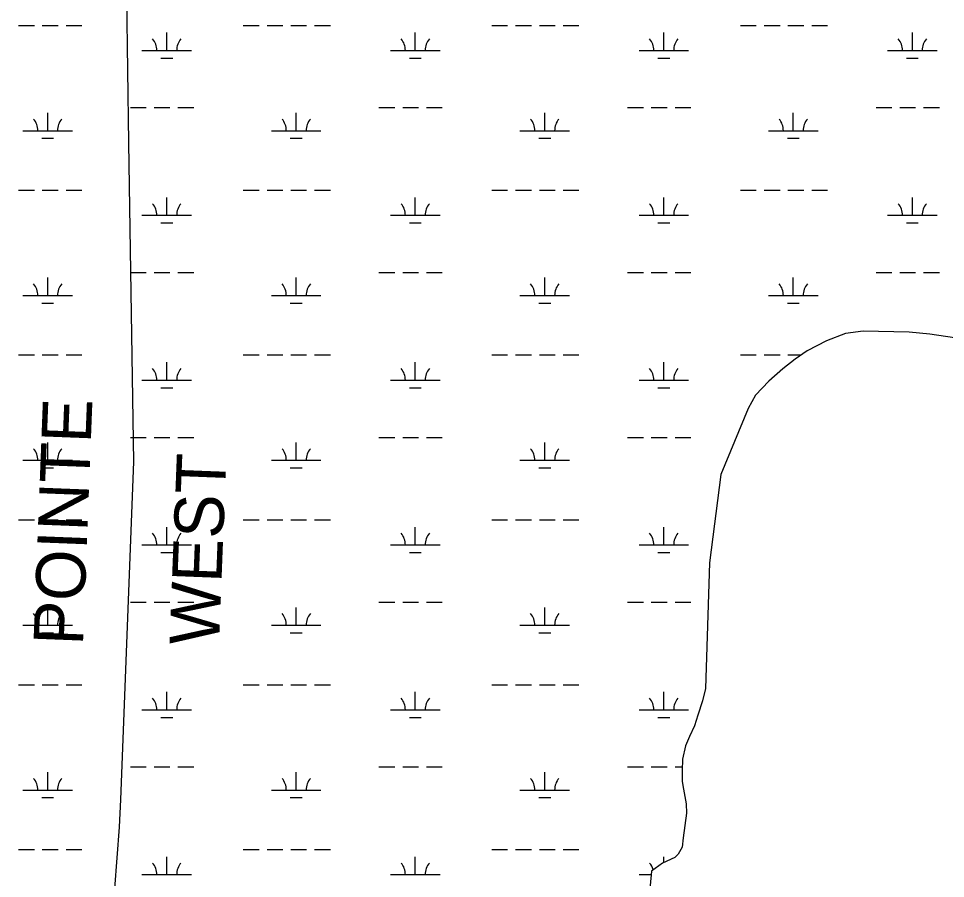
# Model space of a CAD drawing. Extents: x 3161564 to 3199464, y 849354 to 874788.
# Drawn here: x 3177599 to 3179471, y 861984 to 863719 of the extents above; entities that cross this region are included whole.
import ezdxf

# ---------------------------------------------------------------- set-up
doc = ezdxf.new("R2010")
doc.units = 0
for name, color, linetype in [('V-TOPO-BNDY', 7, 'Continuous'), ('V-TOPO-GNAM-IDEN', 7, 'Continuous'), ('V-WETL-SWMP', 7, 'Continuous')]:
    doc.layers.add(name, color=color, linetype=linetype)

msp = doc.modelspace()

# ---------------------------------------------------------------- linework, layer by layer
at = {"layer": 'V-TOPO-BNDY'}
for p, q in [((3177821.5, 863468.4), (3177816.7, 863804.9)), ((3177823.9, 863294.4), (3177821.5, 863468.4)), ((3177831.7, 862824.6), (3177823.9, 863294.4)), ((3177804.9, 862143), (3177831.7, 862824.6)), ((3177802.7, 862086.9), (3177804.9, 862143)), ((3177793, 861963), (3177802.7, 862086.9))]:
    msp.add_line(p, q, dxfattribs=at)
at = {"layer": 'V-WETL-SWMP'}
for p, q in [((3177598.6, 863705.4), (3177630.6, 863705.4)), ((3177646.6, 863705.4), (3177678.6, 863705.4)), ((3177694.6, 863705.4), (3177726.6, 863705.4)), ((3178052.5, 863705.4), (3178084.5, 863705.4)), ((3178100.5, 863705.4), (3178132.5, 863705.4)), ((3178148.5, 863705.4), (3178180.5, 863705.4)), ((3178196.5, 863705.4), (3178228.5, 863705.4)), ((3178554.4, 863705.4), (3178586.4, 863705.4)), ((3178602.4, 863705.4), (3178634.4, 863705.4)), ((3178650.4, 863705.4), (3178682.4, 863705.4)), ((3178698.4, 863705.4), (3178730.4, 863705.4)), ((3179056.4, 863705.4), (3179088.4, 863705.4)), ((3179104.4, 863705.4), (3179136.4, 863705.4)), ((3179152.4, 863705.4), (3179184.4, 863705.4)), ((3179200.4, 863705.4), (3179232.4, 863705.4)), ((3177897.9, 863654.7), (3177897.9, 863690.7)), ((3178399.9, 863654.7), (3178399.9, 863690.7)), ((3178901.8, 863654.7), (3178901.8, 863690.7)), ((3179403.7, 863654.7), (3179403.7, 863690.7)), ((3177847.9, 863654.7), (3177947.9, 863654.7)), ((3177885.9, 863639.3), (3177909.9, 863639.3)), ((3178349.9, 863654.7), (3178449.9, 863654.7)), ((3178387.9, 863639.3), (3178411.9, 863639.3)), ((3178851.8, 863654.7), (3178951.8, 863654.7)), ((3178889.8, 863639.3), (3178913.8, 863639.3)), ((3179353.7, 863654.7), (3179453.7, 863654.7)), ((3179391.7, 863639.3), (3179415.7, 863639.3)), ((3177657.5, 863492.8), (3177657.5, 863528.8)), ((3177824.5, 863539.3), (3177856.5, 863539.3)), ((3177872.5, 863539.3), (3177904.5, 863539.3)), ((3177920.5, 863539.3), (3177952.5, 863539.3)), ((3178159.4, 863492.8), (3178159.4, 863528.8)), ((3178326.4, 863539.3), (3178358.4, 863539.3)), ((3178374.4, 863539.3), (3178406.4, 863539.3)), ((3178422.4, 863539.3), (3178454.4, 863539.3)), ((3178661.3, 863492.8), (3178661.3, 863528.8)), ((3178828.4, 863539.3), (3178860.4, 863539.3)), ((3178876.4, 863539.3), (3178908.4, 863539.3)), ((3178924.4, 863539.3), (3178956.4, 863539.3)), ((3179163.2, 863492.8), (3179163.2, 863528.8)), ((3179330.3, 863539.3), (3179362.3, 863539.3)), ((3179378.3, 863539.3), (3179410.3, 863539.3)), ((3179426.3, 863539.3), (3179458.3, 863539.3)), ((3177607.5, 863492.8), (3177707.5, 863492.8)), ((3178109.4, 863492.8), (3178209.4, 863492.8)), ((3178611.3, 863492.8), (3178711.3, 863492.8)), ((3179113.2, 863492.8), (3179213.2, 863492.8)), ((3177645.5, 863477.4), (3177669.5, 863477.4)), ((3178147.4, 863477.4), (3178171.4, 863477.4)), ((3178649.3, 863477.4), (3178673.3, 863477.4)), ((3179151.2, 863477.4), (3179175.2, 863477.4)), ((3177598.6, 863372.8), (3177630.6, 863372.8)), ((3177646.6, 863372.8), (3177678.6, 863372.8)), ((3177694.6, 863372.8), (3177726.6, 863372.8)), ((3177897.9, 863322), (3177897.9, 863358)), ((3178052.5, 863372.8), (3178084.5, 863372.8)), ((3178100.5, 863372.8), (3178132.5, 863372.8)), ((3178148.5, 863372.8), (3178180.5, 863372.8)), ((3178196.5, 863372.8), (3178228.5, 863372.8)), ((3178399.9, 863322), (3178399.9, 863358)), ((3178554.4, 863372.8), (3178586.4, 863372.8)), ((3178602.4, 863372.8), (3178634.4, 863372.8)), ((3178650.4, 863372.8), (3178682.4, 863372.8)), ((3178698.4, 863372.8), (3178730.4, 863372.8)), ((3178901.8, 863322), (3178901.8, 863358)), ((3179056.4, 863372.8), (3179088.4, 863372.8)), ((3179104.4, 863372.8), (3179136.4, 863372.8)), ((3179152.4, 863372.8), (3179184.4, 863372.8)), ((3179200.4, 863372.8), (3179232.4, 863372.8)), ((3179403.7, 863322), (3179403.7, 863358)), ((3177847.9, 863322), (3177947.9, 863322)), ((3178349.9, 863322), (3178449.9, 863322)), ((3178851.8, 863322), (3178951.8, 863322)), ((3179353.7, 863322), (3179453.7, 863322)), ((3177885.9, 863306.6), (3177909.9, 863306.6)), ((3178387.9, 863306.6), (3178411.9, 863306.6)), ((3178889.8, 863306.6), (3178913.8, 863306.6)), ((3179391.7, 863306.6), (3179415.7, 863306.6)), ((3177657.5, 863160.2), (3177657.5, 863196.2)), ((3177824.5, 863206.6), (3177856.5, 863206.6)), ((3177872.5, 863206.6), (3177904.5, 863206.6)), ((3177920.5, 863206.6), (3177952.5, 863206.6)), ((3178159.4, 863160.2), (3178159.4, 863196.2)), ((3178326.4, 863206.6), (3178358.4, 863206.6)), ((3178374.4, 863206.6), (3178406.4, 863206.6)), ((3178422.4, 863206.6), (3178454.4, 863206.6)), ((3178661.3, 863160.2), (3178661.3, 863196.2)), ((3178828.4, 863206.6), (3178860.4, 863206.6)), ((3178876.4, 863206.6), (3178908.4, 863206.6)), ((3178924.4, 863206.6), (3178956.4, 863206.6)), ((3179163.2, 863160.2), (3179163.2, 863196.2)), ((3179330.3, 863206.6), (3179362.3, 863206.6)), ((3179378.3, 863206.6), (3179410.3, 863206.6)), ((3179426.3, 863206.6), (3179458.3, 863206.6)), ((3177607.5, 863160.2), (3177707.5, 863160.2)), ((3178109.4, 863160.2), (3178209.4, 863160.2)), ((3178611.3, 863160.2), (3178711.3, 863160.2)), ((3179113.2, 863160.2), (3179213.2, 863160.2)), ((3177645.5, 863144.7), (3177669.5, 863144.7)), ((3178147.4, 863144.7), (3178171.4, 863144.7)), ((3178649.3, 863144.7), (3178673.3, 863144.7)), ((3179151.2, 863144.7), (3179175.2, 863144.7)), ((3179268.5, 863083.4), (3179230, 863069)), ((3179304.2, 863087.9), (3179268.5, 863083.4)), ((3179397.1, 863086.2), (3179304.2, 863087.9)), ((3179439.2, 863081.9), (3179397.1, 863086.2)), ((3179488.5, 863074.5), (3179439.2, 863081.9)), ((3179230, 863069), (3179191, 863048.2)), ((3177598.6, 863040.1), (3177630.6, 863040.1)), ((3177646.6, 863040.1), (3177678.6, 863040.1)), ((3177694.6, 863040.1), (3177726.6, 863040.1)), ((3178052.5, 863040.1), (3178084.5, 863040.1)), ((3178100.5, 863040.1), (3178132.5, 863040.1)), ((3178148.5, 863040.1), (3178180.5, 863040.1)), ((3178196.5, 863040.1), (3178228.5, 863040.1)), ((3178554.4, 863040.1), (3178586.4, 863040.1)), ((3178602.4, 863040.1), (3178634.4, 863040.1)), ((3178650.4, 863040.1), (3178682.4, 863040.1)), ((3178698.4, 863040.1), (3178730.4, 863040.1)), ((3179056.4, 863040.1), (3179088.4, 863040.1)), ((3179104.4, 863040.1), (3179136.4, 863040.1)), ((3179152.4, 863040.1), (3179178.9, 863040.1)), ((3179191, 863048.2), (3179166.7, 863031.9)), ((3177897.9, 862989.4), (3177897.9, 863025.4)), ((3178399.9, 862989.4), (3178399.9, 863025.4)), ((3178901.8, 862989.4), (3178901.8, 863025.4)), ((3179166.7, 863031.9), (3179142, 863012.1)), ((3179142, 863012.1), (3179114.1, 862987.5)), ((3177847.9, 862989.4), (3177947.9, 862989.4)), ((3178349.9, 862989.4), (3178449.9, 862989.4)), ((3178851.8, 862989.4), (3178951.8, 862989.4)), ((3179114.1, 862987.5), (3179087.1, 862958.9)), ((3177885.9, 862973.9), (3177909.9, 862973.9)), ((3178387.9, 862973.9), (3178411.9, 862973.9)), ((3178889.8, 862973.9), (3178913.8, 862973.9)), ((3179087.1, 862958.9), (3179072.4, 862932.4)), ((3179072.4, 862932.4), (3179016.9, 862798.6)), ((3177824.5, 862873.9), (3177856.5, 862873.9)), ((3177872.5, 862873.9), (3177904.5, 862873.9)), ((3177920.5, 862873.9), (3177952.5, 862873.9)), ((3178326.4, 862873.9), (3178358.4, 862873.9)), ((3178374.4, 862873.9), (3178406.4, 862873.9)), ((3178422.4, 862873.9), (3178454.4, 862873.9)), ((3178828.4, 862873.9), (3178860.4, 862873.9)), ((3178876.4, 862873.9), (3178908.4, 862873.9)), ((3178924.4, 862873.9), (3178956.4, 862873.9)), ((3177657.5, 862827.5), (3177657.5, 862863.5)), ((3178159.4, 862827.5), (3178159.4, 862863.5)), ((3178661.3, 862827.5), (3178661.3, 862863.5)), ((3177607.5, 862827.5), (3177707.5, 862827.5)), ((3178109.4, 862827.5), (3178209.4, 862827.5)), ((3178611.3, 862827.5), (3178711.3, 862827.5)), ((3177645.5, 862812.1), (3177669.5, 862812.1)), ((3178147.4, 862812.1), (3178171.4, 862812.1)), ((3178649.3, 862812.1), (3178673.3, 862812.1)), ((3179016.9, 862798.6), (3178994.2, 862620.3)), ((3177598.6, 862707.4), (3177630.6, 862707.4)), ((3177646.6, 862707.4), (3177678.6, 862707.4)), ((3177694.6, 862707.4), (3177726.6, 862707.4)), ((3178052.5, 862707.4), (3178084.5, 862707.4)), ((3178100.5, 862707.4), (3178132.5, 862707.4)), ((3178148.5, 862707.4), (3178180.5, 862707.4)), ((3178196.5, 862707.4), (3178228.5, 862707.4)), ((3178554.4, 862707.4), (3178586.4, 862707.4)), ((3178602.4, 862707.4), (3178634.4, 862707.4)), ((3178650.4, 862707.4), (3178682.4, 862707.4)), ((3178698.4, 862707.4), (3178730.4, 862707.4)), ((3177897.9, 862656.7), (3177897.9, 862692.7)), ((3178399.9, 862656.7), (3178399.9, 862692.7)), ((3178901.8, 862656.7), (3178901.8, 862692.7)), ((3177847.9, 862656.7), (3177947.9, 862656.7)), ((3178349.9, 862656.7), (3178449.9, 862656.7)), ((3178851.8, 862656.7), (3178951.8, 862656.7)), ((3177885.9, 862641.2), (3177909.9, 862641.2)), ((3178387.9, 862641.2), (3178411.9, 862641.2)), ((3178889.8, 862641.2), (3178913.8, 862641.2)), ((3178994.2, 862620.3), (3178985.8, 862366.7)), ((3177824.5, 862541.2), (3177856.5, 862541.2)), ((3177872.5, 862541.2), (3177904.5, 862541.2)), ((3177920.5, 862541.2), (3177952.5, 862541.2)), ((3178326.4, 862541.2), (3178358.4, 862541.2)), ((3178374.4, 862541.2), (3178406.4, 862541.2)), ((3178422.4, 862541.2), (3178454.4, 862541.2)), ((3178828.4, 862541.2), (3178860.4, 862541.2)), ((3178876.4, 862541.2), (3178908.4, 862541.2)), ((3178924.4, 862541.2), (3178956.4, 862541.2)), ((3177657.5, 862494.8), (3177657.5, 862530.8)), ((3178159.4, 862494.8), (3178159.4, 862530.8)), ((3178661.3, 862494.8), (3178661.3, 862530.8)), ((3177607.5, 862494.8), (3177707.5, 862494.8)), ((3177645.5, 862479.4), (3177669.5, 862479.4)), ((3178109.4, 862494.8), (3178209.4, 862494.8)), ((3178147.4, 862479.4), (3178171.4, 862479.4)), ((3178611.3, 862494.8), (3178711.3, 862494.8)), ((3178649.3, 862479.4), (3178673.3, 862479.4)), ((3177598.6, 862374.7), (3177630.6, 862374.7)), ((3177646.6, 862374.7), (3177678.6, 862374.7)), ((3177694.6, 862374.7), (3177726.6, 862374.7)), ((3178052.5, 862374.7), (3178084.5, 862374.7)), ((3178100.5, 862374.7), (3178132.5, 862374.7)), ((3178148.5, 862374.7), (3178180.5, 862374.7)), ((3178196.5, 862374.7), (3178228.5, 862374.7)), ((3178554.4, 862374.7), (3178586.4, 862374.7)), ((3178602.4, 862374.7), (3178634.4, 862374.7)), ((3178650.4, 862374.7), (3178682.4, 862374.7)), ((3178698.4, 862374.7), (3178730.4, 862374.7)), ((3178985.8, 862366.7), (3178980, 862342)), ((3177897.9, 862324), (3177897.9, 862360)), ((3178399.9, 862324), (3178399.9, 862360)), ((3178901.8, 862324), (3178901.8, 862360)), ((3178980, 862342), (3178970.3, 862313.2)), ((3177847.9, 862324), (3177947.9, 862324)), ((3178349.9, 862324), (3178449.9, 862324)), ((3178851.8, 862324), (3178951.8, 862324)), ((3178970.3, 862313.2), (3178963.6, 862291.7)), ((3177885.9, 862308.6), (3177909.9, 862308.6)), ((3178387.9, 862308.6), (3178411.9, 862308.6)), ((3178889.8, 862308.6), (3178913.8, 862308.6)), ((3178963.6, 862291.7), (3178953.6, 862269.9)), ((3178953.6, 862269.9), (3178945.4, 862251)), ((3178945.4, 862251), (3178939.6, 862224.6)), ((3178939.6, 862224.6), (3178938.5, 862201.5)), ((3177657.5, 862162.1), (3177657.5, 862198.1)), ((3177824.5, 862208.6), (3177856.5, 862208.6)), ((3177872.5, 862208.6), (3177904.5, 862208.6)), ((3177920.5, 862208.6), (3177952.5, 862208.6)), ((3178159.4, 862162.1), (3178159.4, 862198.1)), ((3178326.4, 862208.6), (3178358.4, 862208.6)), ((3178374.4, 862208.6), (3178406.4, 862208.6)), ((3178422.4, 862208.6), (3178454.4, 862208.6)), ((3178661.3, 862162.1), (3178661.3, 862198.1)), ((3178828.4, 862208.6), (3178860.4, 862208.6)), ((3178876.4, 862208.6), (3178908.4, 862208.6)), ((3178924.4, 862208.6), (3178938.9, 862208.6)), ((3178938.5, 862201.5), (3178938.9, 862179.6)), ((3178938.9, 862179.6), (3178941.4, 862163.9)), ((3177607.5, 862162.1), (3177707.5, 862162.1)), ((3178109.4, 862162.1), (3178209.4, 862162.1)), ((3178611.3, 862162.1), (3178711.3, 862162.1)), ((3178941.4, 862163.9), (3178946.7, 862133.9)), ((3177645.5, 862146.7), (3177669.5, 862146.7)), ((3178147.4, 862146.7), (3178171.4, 862146.7)), ((3178649.3, 862146.7), (3178673.3, 862146.7)), ((3178946.7, 862133.9), (3178947.5, 862115.2)), ((3178947.5, 862115.2), (3178941.1, 862065.5)), ((3178941.1, 862065.5), (3178939.1, 862047)), ((3177598.6, 862042.1), (3177630.6, 862042.1)), ((3177646.6, 862042.1), (3177678.6, 862042.1)), ((3177694.6, 862042.1), (3177726.6, 862042.1)), ((3178052.5, 862042.1), (3178084.5, 862042.1)), ((3178100.5, 862042.1), (3178132.5, 862042.1)), ((3178148.5, 862042.1), (3178180.5, 862042.1)), ((3178196.5, 862042.1), (3178228.5, 862042.1)), ((3178554.4, 862042.1), (3178586.4, 862042.1)), ((3178602.4, 862042.1), (3178634.4, 862042.1)), ((3178650.4, 862042.1), (3178682.4, 862042.1)), ((3178698.4, 862042.1), (3178730.4, 862042.1)), ((3178930.7, 862032.9), (3178923.7, 862026.2)), ((3178939.1, 862047), (3178930.7, 862032.9)), ((3177897.9, 861991.3), (3177897.9, 862027.3)), ((3178399.9, 861991.3), (3178399.9, 862027.3)), ((3178899.4, 862014.5), (3178876.9, 861998.4)), ((3178923.7, 862026.2), (3178899.4, 862014.5)), ((3178901.8, 862015.6), (3178901.8, 862027.3)), ((3177847.9, 861991.3), (3177947.9, 861991.3)), ((3178349.9, 861991.3), (3178449.9, 861991.3)), ((3178851.8, 861991.3), (3178876.2, 861991.3)), ((3178876.9, 861998.4), (3178866.8, 861892.4))]:
    msp.add_line(p, q, dxfattribs=at)
for centre, start, end in [((3177842.7, 863655.2), 359.2282, 40.7718), ((3177953.2, 863655.2), 139.2282, 180.7718), ((3178344.6, 863655.2), 359.2282, 40.7718), ((3178455.1, 863655.2), 139.2282, 180.7718), ((3178846.5, 863655.2), 359.2282, 40.7718), ((3178957, 863655.2), 139.2282, 180.7718), ((3179348.4, 863655.2), 359.2282, 40.7718), ((3179458.9, 863655.2), 139.2282, 180.7718), ((3177602.2, 863493.3), 359.2282, 40.7718), ((3177712.7, 863493.3), 139.2282, 180.7718), ((3178104.1, 863493.3), 359.2282, 40.7718), ((3178214.6, 863493.3), 139.2282, 180.7718), ((3178606.1, 863493.3), 359.2282, 40.7718), ((3178716.5, 863493.3), 139.2282, 180.7718), ((3179108, 863493.3), 359.2282, 40.7718), ((3179218.4, 863493.3), 139.2282, 180.7718), ((3177842.7, 863322.5), 359.2282, 40.7718), ((3177953.2, 863322.5), 139.2282, 180.7718), ((3178344.6, 863322.5), 359.2282, 40.7718), ((3178455.1, 863322.5), 139.2282, 180.7718), ((3178846.5, 863322.5), 359.2282, 40.7718), ((3178957, 863322.5), 139.2282, 180.7718), ((3179348.4, 863322.5), 359.2282, 40.7718), ((3179458.9, 863322.5), 139.2282, 180.7718), ((3177602.2, 863160.6), 359.2282, 40.7718), ((3177712.7, 863160.6), 139.2282, 180.7718), ((3178104.1, 863160.6), 359.2282, 40.7718), ((3178214.6, 863160.6), 139.2282, 180.7718), ((3178606.1, 863160.6), 359.2282, 40.7718), ((3178716.5, 863160.6), 139.2282, 180.7718), ((3179108, 863160.6), 359.2282, 40.7718), ((3179218.4, 863160.6), 139.2282, 180.7718), ((3177842.7, 862989.8), 359.2282, 40.7718), ((3177953.2, 862989.8), 139.2282, 180.7718), ((3178344.6, 862989.8), 359.2282, 40.7718), ((3178455.1, 862989.8), 139.2282, 180.7718), ((3178846.5, 862989.8), 359.2282, 40.7718), ((3178957, 862989.8), 139.2282, 180.7718), ((3177602.2, 862828), 359.2282, 40.7718), ((3177712.7, 862828), 139.2282, 180.7718), ((3178104.1, 862828), 359.2282, 40.7718), ((3178214.6, 862828), 139.2282, 180.7718), ((3178606.1, 862828), 359.2282, 40.7718), ((3178716.5, 862828), 139.2282, 180.7718), ((3177842.7, 862657.2), 359.2282, 40.7718), ((3177953.2, 862657.2), 139.2282, 180.7718), ((3178344.6, 862657.2), 359.2282, 40.7718), ((3178455.1, 862657.2), 139.2282, 180.7718), ((3178846.5, 862657.2), 359.2282, 40.7718), ((3178957, 862657.2), 139.2282, 180.7718), ((3177602.2, 862495.3), 359.2282, 40.7718), ((3177712.7, 862495.3), 139.2282, 180.7718), ((3178104.1, 862495.3), 359.2282, 40.7718), ((3178214.6, 862495.3), 139.2282, 180.7718), ((3178606.1, 862495.3), 359.2282, 40.7718), ((3178716.5, 862495.3), 139.2282, 180.7718), ((3177842.7, 862324.5), 359.2282, 40.7718), ((3177953.2, 862324.5), 139.2282, 180.7718), ((3178344.6, 862324.5), 359.2282, 40.7718), ((3178455.1, 862324.5), 139.2282, 180.7718), ((3178846.5, 862324.5), 359.2282, 40.7718), ((3178957, 862324.5), 139.2282, 180.7718), ((3177602.2, 862162.6), 359.2282, 40.7718), ((3177712.7, 862162.6), 139.2282, 180.7718), ((3178104.1, 862162.6), 359.2282, 40.7718), ((3178214.6, 862162.6), 139.2282, 180.7718), ((3178606.1, 862162.6), 359.2282, 40.7718), ((3178716.5, 862162.6), 139.2282, 180.7718), ((3177842.7, 861991.8), 359.2282, 40.7718), ((3177953.2, 861991.8), 139.2282, 180.7718), ((3178344.6, 861991.8), 359.2282, 40.7718), ((3178455.1, 861991.8), 139.2282, 180.7718), ((3178846.5, 861991.8), 15.2389, 40.7718)]:
    msp.add_arc(centre, 35.2, start, end, dxfattribs=at)

# ---------------------------------------------------------------- texts
at = {"layer": 'V-TOPO-GNAM-IDEN'}
for s, p in [('POINTE', (3177728.6, 862452.7)), ('WEST', (3178003.4, 862453.1))]:
    msp.add_text(s, height=100, rotation=87.7722, dxfattribs=at).set_placement(p)

doc.saveas('drawing.dxf')
